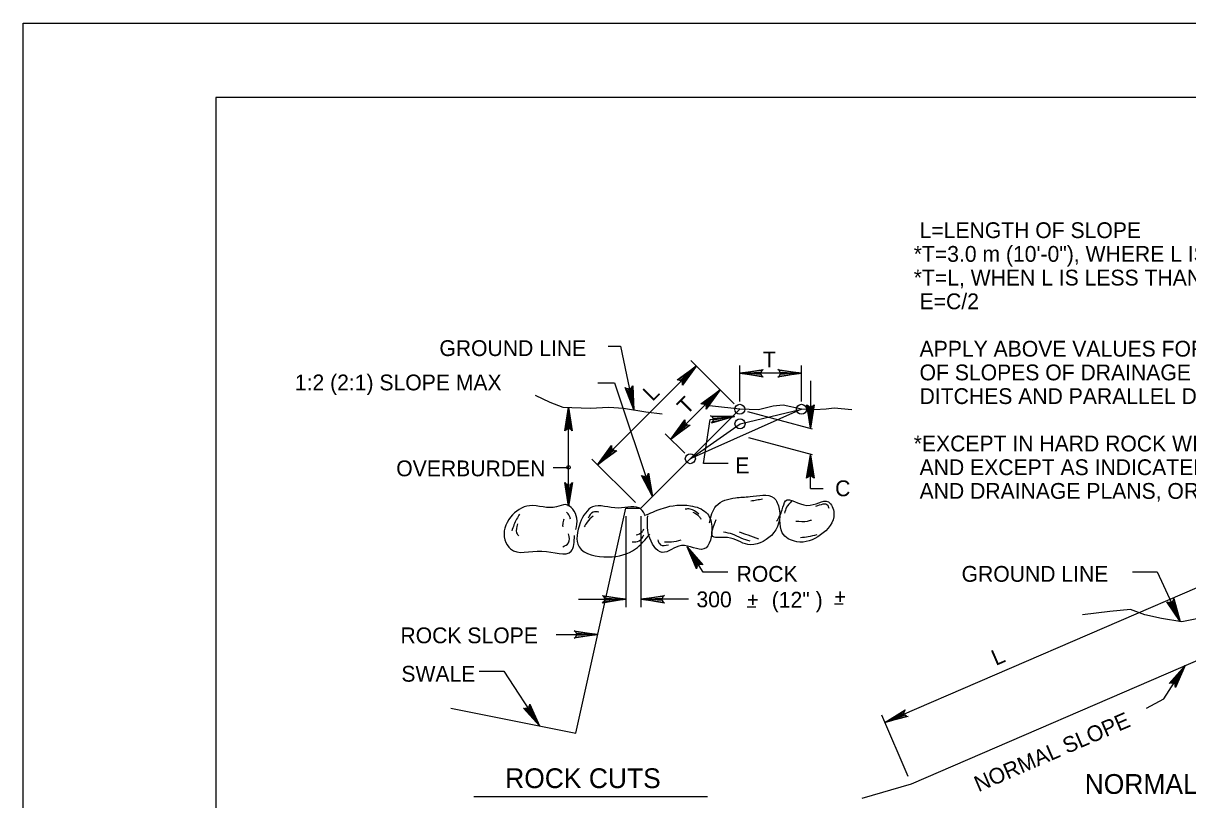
# Model space of a CAD drawing. Extents: x 240 to 1147, y 662 to 1256.
# Drawn here: x 240.4 to 476.2, y 1098.9 to 1256 of the extents above; entities that cross this region are included whole.
import ezdxf

# ---------------------------------------------------------------- set-up
doc = ezdxf.new("R2010")
doc.units = 0
for name, color, linetype in [('1', 7, 'Continuous'), ('2', 7, 'Continuous'), ('3', 7, 'Continuous'), ('PLT-BNDY', 7, 'Continuous')]:
    doc.layers.add(name, color=color, linetype=linetype)

msp = doc.modelspace()

# ---------------------------------------------------------------- linework, layer by layer
at = {"layer": '1'}
for points in [[(1065.4425, 677.018625), (1065.4425, 1241.018625), (279.4425, 1241.018625), (279.4425, 677.018625), (1065.4425, 677.018625), (1065.4425, 703.377625), (865.4425, 703.377625), (865.4425, 768.055125), (1065.4425, 768.055125), (1065.4425, 797.018625), (865.4425, 797.018625), (865.4425, 677.018625), (944.244, 677.018625), (944.244, 703.377625), (944.244, 677.018625), (1021.244, 677.018625), (1021.244, 703.377625), (1021.244, 691.061125), (1065.4425, 691.061125)], [(373.0945, 1183.852125), (373.4465, 1183.739625), (376.709, 1186.660375), (373.0945, 1183.852125), (372.79025, 1183.829125), (376.709, 1186.660375), (373.77375, 1183.418625), (373.89025, 1183.077125), (376.709, 1186.660375), (373.8695, 1182.747875), (373.89025, 1183.077125)], [(390.02775, 1184.595875), (389.859, 1184.922875), (385.48625, 1185.164625), (390.02775, 1184.595875), (390.259, 1184.395875), (385.48625, 1185.164625), (389.855, 1185.381125), (390.01325, 1185.706125), (385.48625, 1185.164625), (390.259, 1185.922875), (390.01325, 1185.706125)], [(393.4465, 1185.735375), (393.61525, 1185.406125), (397.98625, 1185.164625), (393.4465, 1185.735375), (393.21325, 1185.935375), (397.98625, 1185.164625), (393.6195, 1184.949875), (393.459, 1184.622875), (397.98625, 1185.164625), (393.21325, 1184.406125), (393.459, 1184.622875)], [(363.67575, 1182.337375), (363.38825, 1182.104125), (364.034, 1177.774875), (363.67575, 1182.337375), (363.82375, 1182.606125), (364.034, 1177.774875), (362.94025, 1182.008375), (362.59025, 1182.099875), (364.034, 1177.774875), (362.32775, 1182.295875), (362.59025, 1182.099875)], [(377.93825, 1179.008375), (378.29025, 1178.895875), (381.55275, 1181.816625), (377.93825, 1179.008375), (377.634, 1178.985375), (381.55275, 1181.816625), (378.6175, 1178.574875), (378.734, 1178.233375), (381.55275, 1181.816625), (378.71325, 1177.904125), (378.734, 1178.233375)], [(400.38, 1178.585375), (400.05275, 1178.416625), (399.81125, 1174.045875), (400.38, 1178.585375), (400.58, 1178.818625), (399.81125, 1174.045875), (399.5945, 1178.412375), (399.2695, 1178.572875), (399.81125, 1174.045875), (399.05275, 1178.818625), (399.2695, 1178.572875)], [(350.26525, 1173.760375), (350.5945, 1173.929125), (350.83625, 1178.299875), (350.26525, 1173.760375), (350.06525, 1173.527125), (350.83625, 1178.299875), (351.05075, 1173.933375), (351.37575, 1173.772875), (350.83625, 1178.299875), (351.5945, 1173.527125), (351.37575, 1173.772875)], [(379.84875, 1176.422875), (380.06125, 1176.118625), (384.42575, 1176.449875), (379.84875, 1176.422875), (379.5925, 1176.589625), (384.42575, 1176.449875), (380.12375, 1175.664625), (380.009, 1175.322875), (384.42575, 1176.449875), (379.7925, 1175.074875), (380.009, 1175.322875)], [(375.1675, 1174.624875), (374.81525, 1174.737375), (371.55275, 1171.816625), (375.1675, 1174.624875), (375.4715, 1174.647875), (371.55275, 1171.816625), (374.48825, 1175.058375), (374.3715, 1175.399875), (371.55275, 1171.816625), (374.3925, 1175.729125), (374.3715, 1175.399875)], [(360.3215, 1169.468625), (359.9715, 1169.581125), (356.709, 1166.660375), (360.3215, 1169.468625), (360.62775, 1169.491625), (356.709, 1166.660375), (359.6445, 1169.902125), (359.52775, 1170.245875), (356.709, 1166.660375), (359.54875, 1170.572875), (359.52775, 1170.245875)], [(399.24025, 1164.145875), (399.5695, 1164.314625), (399.81125, 1168.687375), (399.24025, 1164.145875), (399.04025, 1163.912375), (399.81125, 1168.687375), (400.02575, 1164.318625), (400.35275, 1164.160375), (399.81125, 1168.687375), (400.5695, 1163.912375), (400.35275, 1164.160375)], [(366.9175, 1164.697875), (366.659, 1164.433375), (367.81525, 1160.210375), (366.9175, 1164.697875), (367.034, 1164.983375), (367.81525, 1160.210375), (366.22775, 1164.285375), (365.8675, 1164.333375), (367.81525, 1160.210375), (365.584, 1164.497875), (365.8675, 1164.333375)], [(351.405, 1162.822875), (351.07575, 1162.654125), (350.83625, 1158.281125), (351.405, 1162.822875), (351.605, 1163.054125), (350.83625, 1158.281125), (350.6195, 1162.649875), (350.2945, 1162.808375), (350.83625, 1158.281125), (350.07775, 1163.054125), (350.2945, 1162.808375)], [(376.80075, 1145.912375), (376.98625, 1146.233375), (374.834, 1150.045875), (376.80075, 1145.912375), (376.757, 1145.610375), (374.834, 1150.045875), (377.3695, 1146.481125), (377.73, 1146.522875), (374.834, 1150.045875), (378.0445, 1146.433375), (377.73, 1146.522875)], [(357.909, 1139.989625), (358.07775, 1139.660375), (362.44875, 1139.418625), (357.909, 1139.989625), (357.67575, 1140.187375), (362.44875, 1139.418625), (358.082, 1139.202125), (357.9215, 1138.877125), (362.44875, 1139.418625), (357.67575, 1138.660375), (357.9215, 1138.877125)], [(370.02775, 1138.847875), (369.859, 1139.177125), (365.48625, 1139.418625), (370.02775, 1138.847875), (370.259, 1138.649875), (365.48625, 1139.418625), (369.855, 1139.635375), (370.01325, 1139.960375), (365.48625, 1139.418625), (370.259, 1140.177125), (370.01325, 1139.960375)], [(473.27775, 1139.279125), (473.05075, 1138.985375), (474.6715, 1134.918625), (473.27775, 1139.279125), (473.36125, 1139.572875), (474.6715, 1134.918625), (472.63825, 1138.791625), (472.27575, 1138.797875), (474.6715, 1134.918625), (471.97575, 1138.929125), (472.27575, 1138.797875)], [(352.2215, 1132.864625), (352.39025, 1132.535375), (356.76325, 1132.295875), (352.2215, 1132.864625), (351.99025, 1133.064625), (356.76325, 1132.295875), (352.3945, 1132.079125), (352.23625, 1131.754125), (356.76325, 1132.295875), (351.99025, 1131.537375), (352.23625, 1131.754125)], [(472.73625, 1122.495875), (473.105, 1122.460375), (475.67375, 1126.006125), (472.73625, 1122.495875), (472.4425, 1122.408375), (475.67375, 1126.006125), (473.49025, 1122.214625), (473.67775, 1121.906125), (475.67375, 1126.006125), (473.72775, 1121.581125), (473.67775, 1121.906125)], [(342.93625, 1117.922875), (342.75275, 1117.602125), (344.92375, 1113.799875), (342.93625, 1117.922875), (342.97775, 1118.227125), (344.92375, 1113.799875), (342.3695, 1117.349875), (342.009, 1117.308375), (344.92375, 1113.799875), (341.6945, 1117.397875), (342.009, 1117.308375)], [(419.27575, 1115.764625), (418.99025, 1115.999875), (414.882, 1114.487375), (419.27575, 1115.764625), (419.5695, 1115.672875), (414.882, 1114.487375), (418.807, 1116.416625), (418.82375, 1116.779125), (414.882, 1114.487375), (418.96325, 1117.077125), (418.82375, 1116.779125)]]:
    msp.add_lwpolyline(points, dxfattribs=at)
at = {"layer": '2'}
for p, q in [((376.709, 1186.660375), (356.709, 1166.660375)), ((384.355, 1179.014625), (375.57775, 1187.791625)), ((385.48625, 1179.483375), (385.48625, 1186.764625)), ((397.98625, 1179.483375), (397.98625, 1186.764625)), ((397.98625, 1185.164625), (385.48625, 1185.164625)), ((399.81125, 1183.645875), (399.81125, 1174.045875)), ((381.55275, 1181.816625), (371.55275, 1171.816625)), ((350.83625, 1158.281125), (350.83625, 1178.299875)), ((375.48625, 1167.883375), (385.48625, 1177.883375)), ((397.98625, 1177.883375), (375.48625, 1167.883375)), ((385.5465, 1174.933375), (397.98625, 1177.883375)), ((387.032, 1177.468625), (400.157, 1173.952125)), ((375.48625, 1167.883375), (385.5465, 1174.933375)), ((374.355, 1169.014625), (370.4215, 1172.947875)), ((387.282, 1172.156125), (400.159, 1168.706125)), ((364.355, 1159.014625), (355.57775, 1167.791625)), ((365.48625, 1157.883375), (375.48625, 1167.883375)), ((399.81125, 1161.866625), (399.81125, 1168.687375)), ((399.81125, 1161.866625), (402.38825, 1161.866625)), ((362.44875, 1156.283375), (362.44875, 1137.818625)), ((365.48625, 1156.283375), (365.48625, 1137.818625)), ((492.12375, 1147.854125), (414.882, 1114.487375)), ((352.84875, 1139.418625), (362.44875, 1139.418625)), ((375.08625, 1139.418625), (365.48625, 1139.418625)), ((386.98, 1137.897875), (388.734, 1137.897875)), ((404.66625, 1138.516375), (406.42025, 1138.516375)), ((419.61525, 1103.531125), (414.2465, 1115.956125)), ((331.634, 1099.502125), (378.98, 1099.502125))]:
    msp.add_line(p, q, dxfattribs=at)
for points in [[(358.882, 1190.629125), (361.382, 1190.629125), (364.034, 1177.774875)], [(356.76975, 1183.241625), (360.132, 1183.241625), (367.81525, 1160.210375)], [(344.0925, 1180.752125), (347.0675, 1179.345875), (349.6445, 1178.343625), (355.19875, 1178.143625), (358.9675, 1178.343625), (361.9425, 1178.143625), (366.505, 1177.339625), (369.76325, 1176.952125)], [(408.157, 1177.741625), (404.58625, 1178.143625), (403.00075, 1177.941625), (400.6195, 1177.741625), (397.98625, 1177.883375), (394.27375, 1178.743625), (392.29025, 1178.543625), (389.31525, 1177.741625), (385.48625, 1177.883375), (379.9925, 1178.543625), (378.684, 1178.614625)], [(383.1425, 1166.937375), (378.1425, 1166.937375), (379.509, 1175.802125), (384.42575, 1176.449875)], [(347.734, 1166.129125), (350.83625, 1166.129125)], [(327.01125, 1117.383375), (352.32375, 1112.320875), (362.44875, 1157.883375), (365.48625, 1157.883375)], [(383.10275, 1144.933375), (378.10275, 1144.933375), (374.834, 1150.045875)], [(464.9945, 1145.002125), (469.9945, 1145.002125), (474.6715, 1134.918625)], [(478.3965, 1135.568625), (475.00275, 1134.862375), (470.88, 1135.568625), (467.484, 1136.274875), (464.57375, 1137.335375), (460.45075, 1136.983375), (454.87375, 1136.274875)], [(348.31125, 1132.295875), (356.76325, 1132.295875)], [(410.24875, 1099.183375), (420.24875, 1102.062375), (480.24875, 1127.983375)], [(332.74025, 1124.906125), (337.74025, 1124.906125), (344.92375, 1113.799875)], [(467.855, 1117.358375), (471.34875, 1119.287375), (475.67375, 1126.006125)]]:
    msp.add_lwpolyline(points, dxfattribs=at)
for centre, radius in [((385.486583, 1177.882875), 1.015435), ((397.986583, 1177.882875), 1.015435), ((385.545583, 1174.932625), 1.015435), ((375.486583, 1167.882875), 1.015435), ((350.835333, 1166.129125), 0.3585)]:
    msp.add_circle(centre, radius, dxfattribs=at)
for points in [[(379.384, 1154.904125), (380.75075, 1158.360375), (384.6215, 1159.972875), (387.582, 1160.204125), (392.36525, 1159.972875), (393.50275, 1157.668625), (391.909, 1152.370875), (387.12775, 1150.527125), (383.02775, 1151.910375), (380.0675, 1152.139625), (380.75075, 1155.595875)], [(392.95275, 1155.212375), (394.09025, 1157.516625), (394.77375, 1159.360375), (399.10075, 1158.437375), (403.42775, 1159.129125), (404.5675, 1156.824875), (401.834, 1152.447875), (397.05075, 1151.066625), (394.09025, 1152.910375), (393.63625, 1155.443625)], [(352.284, 1153.522875), (352.51125, 1155.827125), (350.234, 1158.591625), (348.41325, 1158.129125), (342.9465, 1158.360375), (339.07575, 1156.056125), (337.93625, 1151.449875), (339.07575, 1149.606125), (345.45275, 1149.145875), (351.37375, 1149.145875), (352.057, 1152.370875)], [(366.40275, 1156.287375), (365.4925, 1157.668625), (360.93825, 1157.899875), (355.70075, 1158.129125), (353.1945, 1154.904125), (352.9675, 1150.066625), (358.88825, 1147.993625), (364.355, 1149.606125), (367.31525, 1152.602125)], [(366.632, 1156.516625), (370.0465, 1157.899875), (375.51325, 1158.360375), (378.70075, 1156.979125), (379.84025, 1154.214625), (378.2465, 1149.606125), (373.69025, 1150.297875), (369.8195, 1148.914625), (367.08625, 1152.370875), (366.859, 1156.287375)], [(377.21525, 1156.674875), (375.43, 1157.677125), (374.43825, 1157.677125)], [(390.107, 1159.683375), (388.9175, 1159.483375), (387.72775, 1159.283375)], [(395.96125, 1159.254125), (394.9695, 1158.049875), (394.57375, 1156.845875)], [(400.92575, 1158.249875), (403.307, 1158.449875), (403.505, 1157.847875)], [(340.9175, 1156.674875), (340.32375, 1155.670875), (339.332, 1153.262375)], [(349.8445, 1155.670875), (349.6445, 1154.666625), (349.6445, 1154.066625)], [(351.232, 1155.670875), (351.034, 1156.272875), (350.43825, 1157.074875)], [(355.7945, 1156.272875), (354.60275, 1155.068625), (354.009, 1154.066625)], [(356.984, 1157.074875), (355.7945, 1157.074875), (354.80275, 1155.870875)], [(376.02575, 1157.074875), (377.21525, 1156.272875), (377.61125, 1155.670875)], [(396.85075, 1155.268625), (399.232, 1155.268625), (400.02575, 1155.470875)], [(340.5215, 1154.666625), (340.32375, 1152.862375), (340.7195, 1152.260375)], [(364.5215, 1152.460375), (365.71125, 1153.062375), (366.107, 1153.664625)], [(382.17375, 1153.062375), (383.959, 1152.660375), (385.7445, 1151.858375), (387.53, 1151.256125)], [(385.3465, 1153.062375), (387.132, 1152.460375), (389.31525, 1151.658375)], [(349.6445, 1150.052125), (350.83625, 1150.856125), (350.83625, 1152.660375)], [(363.72775, 1151.056125), (365.11525, 1151.256125), (366.107, 1152.460375)], [(368.884, 1151.458375), (369.48, 1150.454125), (371.0675, 1150.454125)], [(370.27375, 1151.056125), (371.66125, 1151.056125), (373.6445, 1151.458375)], [(397.79025, 1151.937375), (399.37775, 1152.137375), (401.16125, 1152.539625)]]:
    msp.add_spline(points, degree=3, dxfattribs=at)
at = {"layer": 'PLT-BNDY'}
msp.add_lwpolyline([(240.4425, 1256.018625), (1081.4425, 1256.018625), (1081.4425, 662.018625), (240.4425, 662.018625)], close=True, dxfattribs=at)

# ---------------------------------------------------------------- texts
at = {"layer": '1'}
msp.add_text('(12" )', height=3.1999995, dxfattribs=at).set_placement((391.965, 1137.734875))
at = {"layer": '2'}
for s, height, p in [('T', 3.199988, (390.19875, 1186.364625)), ('OVERBURDEN', 3.1999875, (315.94875, 1164.322875)), ('E', 3.199988, (384.60275, 1164.937375)), ('C', 3.199988, (404.80275, 1160.287375)), ('300', 3.1999995, (376.7285, 1137.808375)), ('+', 2.999986, (404.66, 1138.487125)), ('+', 2.999986, (386.97375, 1137.868625))]:
    msp.add_text(s, height=height, dxfattribs=at).set_placement(p)
for s, height, rotation, p in [('L', 3.199988, 45, (367.80275, 1179.337375)), ('T', 3.199988, 45, (374.7675, 1176.618625)), ('L', 3.199988, 23.36434167, (437.32375, 1125.924875)), ('NORMAL SLOPE', 3.1999875, 23.36434167, (433.82775, 1100.370875))]:
    msp.add_text(s, height=height, rotation=rotation, dxfattribs=at).set_placement(p)
at = {"layer": '3'}
for s, height, p in [(' L=LENGTH OF SLOPE', 3.1999875, (420.71325, 1212.535375)), ('*T=3.0 m (10\'-0"), WHERE L IS 3.0 m (10\'-0") OR GREATER.', 3.1999995, (420.71325, 1207.737625)), ('*T=L, WHEN L IS LESS THAN 3.0 m (10\'-0")', 3.1999995, (420.71325, 1202.939875)), (' E=C/2', 3.1999875, (420.71325, 1198.142125)), ('GROUND LINE', 3.1999875, (324.682, 1188.664625)), (' APPLY ABOVE VALUES FOR ROUNDING THE TOP', 3.1999875, (420.71325, 1188.546625)), (' OF SLOPES OF DRAINAGE SWALES, CHANNELS,', 3.1999875, (420.71325, 1183.748875)), ('1:2 (2:1) SLOPE MAX', 3.1999995, (295.4185, 1181.718375)), (' DITCHES AND PARALLEL DITCHES.', 3.1999875, (420.71325, 1178.951125)), ('*EXCEPT IN HARD ROCK WITHOUT OVERBURDEN,', 3.1999875, (420.71325, 1169.355625)), (' AND EXCEPT AS INDICATED ON CONTOUR GRADING', 3.1999875, (420.71325, 1164.557875)), (' AND DRAINAGE PLANS, OR CROSS SECTIONS.', 3.1999875, (420.71325, 1159.760125)), ('ROCK', 3.1999875, (384.8465, 1142.970875)), ('GROUND LINE', 3.1999875, (430.405, 1142.970875)), ('ROCK SLOPE', 3.1999875, (316.80075, 1130.524875)), ('SWALE', 3.1999875, (316.9925, 1122.747875)), ('ROCK CUTS', 3.999987, (337.99875, 1101.208375)), ('NORMAL CUTS', 3.999987, (455.32375, 1100.041625))]:
    msp.add_text(s, height=height, dxfattribs=at).set_placement(p)

doc.saveas('drawing.dxf')
